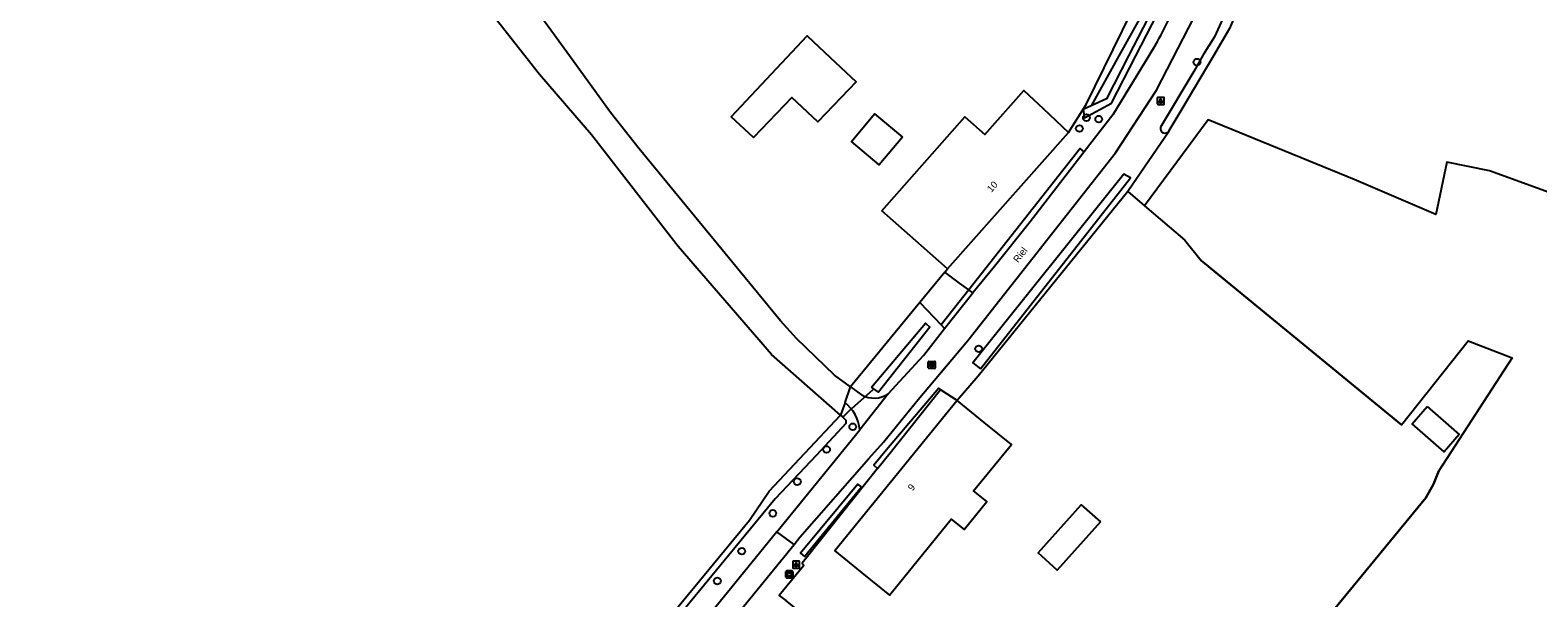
# Model space of a CAD drawing. Extents: x 163863 to 164644, y 379566 to 382155.
# Drawn here: x 164245.6 to 164462.3, y 381172.1 to 381253.7 of the extents above; entities that cross this region are included whole.
import ezdxf

# ---------------------------------------------------------------- set-up
doc = ezdxf.new("R2010")
doc.units = 0
for name, color, linetype in [('IMGEO_Boom', 7, 'Continuous'), ('IMGEO_Duiker', 7, 'Continuous'), ('IMGEO_Erf', 7, 'Continuous'), ('IMGEO_Grasland_agrarisch', 7, 'Continuous'), ('IMGEO_Grasland_overig', 7, 'Continuous'), ('IMGEO_Groenvoorziening', 7, 'Continuous'), ('IMGEO_Haag', 7, 'Continuous'), ('IMGEO_Hek', 7, 'Continuous'), ('IMGEO_Lichtpunt', 7, 'Continuous'), ('IMGEO_Openbare_ruimte_label', 7, 'Continuous'), ('IMGEO_Pand', 7, 'Continuous'), ('IMGEO_Pand_nummerreeks', 7, 'Continuous'), ('IMGEO_Rijbaan_lokaal_gesloten', 7, 'Continuous'), ('IMGEO_Rijbaan_lokaal_halfverhard', 7, 'Continuous'), ('IMGEO_Rioolput', 7, 'Continuous'), ('IMGEO_Verklikker', 7, 'Continuous'), ('IMGEO_Voetpad_gesloten', 7, 'Continuous'), ('IMGEO_Voetpad_open', 7, 'Continuous'), ('IMGEO_Waterloop', 7, 'Continuous')]:
    doc.layers.add(name, color=color, linetype=linetype)

msp = doc.modelspace()

# ---------------------------------------------------------------- linework, layer by layer
at = {"layer": 'IMGEO_Boom'}
for centre in [(164413.32, 381249.11), (164397.44, 381241.12), (164396.42, 381239.57), (164399.21, 381240.92), (164381.95, 381207.91), (164363.86, 381196.71), (164360.09, 381193.46), (164355.88, 381188.82), (164352.37, 381184.28), (164347.89, 381178.84), (164344.39, 381174.56)]:
    msp.add_circle(centre, 0.489, dxfattribs=at)
at = {"layer": 'IMGEO_Duiker'}
msp.add_lwpolyline([(164362.45, 381198.09), (164363.27, 381198.97), (164366.81, 381202.09)], dxfattribs=at)
at = {"layer": 'IMGEO_Erf'}
msp.add_lwpolyline([(164403.37, 381230.53), (164405.79, 381228.47)], dxfattribs=at)
at = {"layer": 'IMGEO_Grasland_agrarisch'}
for points in [[(164491.42, 381190.96), (164476.78, 381197.2), (164466.17, 381201.68), (164468.67, 381207.69), (164476.57, 381225.79), (164455.37, 381233.49), (164449.22, 381234.75), (164447.64, 381227.22), (164435.91, 381232.23), (164414.92, 381240.8), (164405.79, 381228.47)], [(164405.79, 381228.47), (164411.58, 381223.53), (164413.91, 381220.59), (164442.73, 381196.98), (164452.32, 381209.05), (164458.6, 381206.61), (164448.06, 381190.36), (164447.34, 381188.47), (164446.23, 381186.49), (164431.84, 381169.01), (164404.86, 381131.61), (164354.22, 381171.73)]]:
    msp.add_lwpolyline(points, dxfattribs=at)
at = {"layer": 'IMGEO_Grasland_overig'}
for points in [[(164362.1, 381198.39), (164352.18, 381207.09), (164338.77, 381222.6), (164326.32, 381238.65), (164318.83, 381247.33), (164310.33, 381258.14), (164307.18, 381263.52), (164299.42, 381274.81), (164284.28, 381292.99), (164286.58, 381295.47)], [(164363.54, 381202.45), (164361.21, 381204.13), (164355.77, 381209.41), (164353.46, 381211.92), (164333.15, 381236.67), (164329.04, 381241.88), (164323.16, 381250), (164316.87, 381258.7), (164310.95, 381266.61)], [(164394.86, 381239.02), (164397.4, 381243.03), (164407.78, 381264.26)], [(164377.08, 381218.93), (164377.46, 381219.39)], [(164373.51, 381214.58), (164363.54, 381202.45)], [(164362.74, 381200.21), (164362.1, 381198.39)]]:
    msp.add_lwpolyline(points, dxfattribs=at)
at = {"layer": 'IMGEO_Groenvoorziening'}
for points in [[(164409.26, 381239.26), (164409.33, 381239.2), (164403.37, 381230.53)], [(164403.37, 381230.53), (164381.86, 381203.99), (164378.85, 381200.5)], [(164378.85, 381200.5), (164376.58, 381201.96), (164376.48, 381202.06)], [(164367.41, 381190.7), (164357.36, 381178.07), (164356.6, 381177.11), (164356.84, 381176.79), (164353.3, 381172.46), (164354.22, 381171.73)]]:
    msp.add_lwpolyline(points, dxfattribs=at)
at = {"layer": 'IMGEO_Haag'}
msp.add_lwpolyline([(164411.34, 381270.45), (164408.93, 381262.31), (164402.11, 381250), (164398.13, 381242.82)], dxfattribs=at)
at = {"layer": 'IMGEO_Hek'}
for points in [[(164449.22, 381234.75), (164447.64, 381227.22), (164435.91, 381232.23), (164414.92, 381240.8)], [(164468.67, 381207.69), (164476.57, 381225.79), (164455.37, 381233.49), (164449.22, 381234.75)], [(164411.58, 381223.53), (164413.91, 381220.59)], [(164442.73, 381196.98), (164413.91, 381220.59)], [(164406.25, 381130.51), (164427.31, 381160.02), (164428.98, 381161.55), (164431.84, 381169.01), (164446.23, 381186.49), (164447.34, 381188.47), (164448.06, 381190.36)]]:
    msp.add_lwpolyline(points, dxfattribs=at)
at = {"layer": 'IMGEO_Lichtpunt'}
for p, q in [((164407.62, 381243.94), (164407.62, 381243.13)), ((164407.62, 381243.94), (164407.62, 381243.13)), ((164408.52, 381244.03), (164407.71, 381244.03)), ((164408.52, 381244.03), (164407.71, 381244.03)), ((164408.61, 381243.13), (164408.61, 381243.94)), ((164408.61, 381243.13), (164408.61, 381243.94)), ((164407.71, 381243.03), (164408.52, 381243.03)), ((164407.71, 381243.03), (164408.52, 381243.03)), ((164355.22, 381177.3), (164355.22, 381176.5)), ((164355.22, 381177.3), (164355.22, 381176.5)), ((164356.12, 381177.4), (164355.32, 381177.4)), ((164356.12, 381177.4), (164355.32, 381177.4)), ((164356.22, 381176.5), (164356.22, 381177.3)), ((164356.22, 381176.5), (164356.22, 381177.3)), ((164355.32, 381176.4), (164356.12, 381176.4)), ((164355.32, 381176.4), (164356.12, 381176.4))]:
    msp.add_line(p, q, dxfattribs=at)
for points in [[(164407.99, 381243.6), (164408.03, 381243.57), (164407.84, 381243.31), (164407.8, 381243.34), (164407.99, 381243.6)], [(164408.09, 381243.55), (164408.14, 381243.55), (164408.14, 381243.23), (164408.09, 381243.23), (164408.09, 381243.55)], [(164408.2, 381243.57), (164408.24, 381243.6), (164408.43, 381243.34), (164408.39, 381243.31), (164408.2, 381243.57)], [(164355.6, 381176.97), (164355.63, 381176.94), (164355.45, 381176.68), (164355.41, 381176.71), (164355.6, 381176.97)], [(164355.7, 381176.92), (164355.74, 381176.92), (164355.74, 381176.6), (164355.7, 381176.6), (164355.7, 381176.92)], [(164355.81, 381176.94), (164355.85, 381176.97), (164356.03, 381176.7), (164355.99, 381176.68), (164355.81, 381176.94)]]:
    msp.add_lwpolyline(points, dxfattribs=at)
for centre in [(164408.12, 381243.73), (164355.72, 381177.1)]:
    msp.add_circle(centre, 0.0994, dxfattribs=at)
for centre, start, end in [((164407.71, 381243.94), 90, 180), ((164407.71, 381243.94), 90, 180), ((164408.52, 381243.94), 0, 90), ((164408.52, 381243.94), 0, 90), ((164407.71, 381243.13), 180, 270), ((164407.71, 381243.13), 180, 270), ((164408.52, 381243.13), 270, 0), ((164408.52, 381243.13), 270, 360), ((164355.32, 381177.3), 90, 180), ((164355.32, 381177.3), 90, 180), ((164356.12, 381177.3), 0, 90), ((164356.12, 381177.3), 0, 90), ((164355.32, 381176.5), 180, 270), ((164355.32, 381176.5), 180, 270), ((164356.12, 381176.5), 270, 0), ((164356.12, 381176.5), 270, 360)]:
    msp.add_arc(centre, 0.0946, start, end, dxfattribs=at)
at = {"layer": 'IMGEO_Pand'}
for points in [[(164360.62, 381249.78), (164364.35, 381246.28), (164358.84, 381240.52), (164355.11, 381244.02), (164349.6, 381238.26), (164346.39, 381241.26), (164357.3, 381252.89), (164360.62, 381249.78)], [(164377.46, 381219.39), (164373.72, 381222.71), (164368.02, 381227.76), (164379.96, 381241.24), (164382.83, 381238.7), (164388.45, 381245.03), (164391.21, 381242.44), (164394.86, 381239.02)], [(164370.99, 381238.31), (164367.66, 381234.34), (164363.67, 381237.69), (164367, 381241.66), (164370.99, 381238.31)], [(164377.46, 381219.39), (164394.86, 381239.02)], [(164378.85, 381200.5), (164361.29, 381178.9), (164365.17, 381175.74), (164369.12, 381172.53), (164378.01, 381183.46), (164379.86, 381181.95), (164383.12, 381185.97), (164381.23, 381187.51), (164386.65, 381194.16), (164382.73, 381197.35), (164378.85, 381200.5)], [(164446.39, 381199.62), (164451, 381195.59), (164448.83, 381193.12), (164444.23, 381197.15), (164446.39, 381199.62)], [(164399.44, 381183.05), (164393.25, 381176.13), (164390.5, 381178.6), (164396.68, 381185.51), (164399.44, 381183.05)]]:
    msp.add_lwpolyline(points, dxfattribs=at)
at = {"layer": 'IMGEO_Rijbaan_lokaal_gesloten'}
for points in [[(164355.42, 381179.8), (164356.26, 381180.83), (164366.18, 381192.15), (164368.28, 381194.51), (164373.24, 381200.61), (164380.37, 381209.13), (164401.6, 381236.08), (164407.49, 381245.09), (164413.63, 381256.97), (164417.3, 381265.29), (164423.08, 381279.48), (164426.2, 381287.59), (164428.15, 381292.04), (164429.94, 381295.69), (164431.96, 381299.66)], [(164407.38, 381251.61), (164406.39, 381250), (164401.21, 381241.55), (164397.1, 381236.21)], [(164397.1, 381236.21), (164389.34, 381226.14), (164384.21, 381219.76), (164381.13, 381215.96)], [(164377.04, 381210.81), (164381.13, 381215.96)], [(164368.94, 381201.43), (164374.03, 381206.95), (164377.04, 381210.81)], [(164368.94, 381201.43), (164364.89, 381196.29)], [(164352.96, 381181.62), (164364.89, 381196.29)], [(164352.96, 381181.62), (164325.21, 381147.51), (164297.15, 381112.5), (164283.09, 381094.56), (164268.85, 381076.08), (164254.82, 381057.26), (164245.63, 381044.28)], [(164355.42, 381179.8), (164352.96, 381181.62)], [(164246.03, 381039.89), (164248.19, 381042.64), (164257.14, 381055.39), (164271.16, 381074.14), (164285.34, 381092.57), (164299.26, 381110.37), (164327.62, 381145.68), (164355.42, 381179.8)]]:
    msp.add_lwpolyline(points, dxfattribs=at)
msp.add_arc((164356.13, 381281.24), 59.19, 329.9611, 338.3322, dxfattribs=at)
at = {"layer": 'IMGEO_Rijbaan_lokaal_halfverhard'}
for points in [[(164362.74, 381200.21), (164363.54, 381202.45)], [(164363.54, 381202.45), (164365.13, 381201.29)]]:
    msp.add_lwpolyline(points, dxfattribs=at)
for centre, radius, start, end in [((164366.92, 381204.52), 3.69, 241.068, 303.2332), ((164358.9, 381195.56), 6.03, 6.9415, 50.4634)]:
    msp.add_arc(centre, radius, start, end, dxfattribs=at)
at = {"layer": 'IMGEO_Rioolput'}
for p, q in [((164374.69, 381205.18), (164374.69, 381206.03)), ((164374.77, 381206.1), (164375.62, 381206.1)), ((164375.62, 381205.1), (164374.77, 381205.1)), ((164375.18, 381205.88), (164375.21, 381205.88)), ((164375.2, 381205.32), (164375.18, 381205.32)), ((164375.7, 381206.03), (164375.7, 381205.18))]:
    msp.add_line(p, q, dxfattribs=at)
for points in [[(164374.69, 381205.18), (164374.69, 381206.03)], [(164374.77, 381206.1), (164375.62, 381206.1)], [(164375.62, 381205.1), (164374.77, 381205.1)], [(164375.28, 381205.8), (164375.03, 381205.8), (164375.03, 381205.4)], [(164375.03, 381205.4), (164375.16, 381205.4), (164375.16, 381205.57), (164375.17, 381205.57)], [(164375.21, 381205.72), (164375.16, 381205.72), (164375.16, 381205.64)], [(164375.16, 381205.64), (164375.21, 381205.64)], [(164375.21, 381205.54), (164375.28, 381205.4), (164375.42, 381205.4), (164375.36, 381205.53)], [(164375.7, 381206.03), (164375.7, 381205.18)]]:
    msp.add_lwpolyline(points, dxfattribs=at)
for centre, radius, start, end in [((164374.77, 381206.03), 0.0765, 91.552, 178.448), ((164374.77, 381206.03), 0.0765, 91.552, 178.448), ((164374.77, 381205.18), 0.0765, 181.552, 268.448), ((164374.77, 381205.18), 0.0765, 181.552, 268.448), ((164375.16, 381205.51), 0.0533, 26.0293, 88.6989), ((164375.21, 381205.63), 0.0964, 77.0061, 93.1865), ((164375.19, 381205.83), 0.19, 274.7715, 282.9687), ((164375.23, 381205.68), 0.0378, 276.6634, 79.6772), ((164375.28, 381205.69), 0.109, 350.3612, 89.416), ((164375.28, 381205.69), 0.112, 277.5842, 350.9817), ((164375.26, 381205.48), 0.108, 29.5134, 73.7905), ((164375.62, 381206.03), 0.0765, 1.552, 88.448), ((164375.62, 381206.03), 0.0765, 1.552, 88.448), ((164375.62, 381205.18), 0.0765, 271.552, 358.448), ((164375.62, 381205.18), 0.0765, 271.552, 358.448)]:
    msp.add_arc(centre, radius, start, end, dxfattribs=at)
for centre, major_axis, ratio, start_param, end_param in [((164375.18, 381205.6), (-0.387, 0.002), 0.722429, 4.712389, 7.853982), ((164375.21, 381205.6), (-0.39, 0.002), 0.717154, 1.570796, 4.712389)]:
    msp.add_ellipse(centre, major_axis=major_axis, ratio=ratio, start_param=start_param, end_param=end_param, dxfattribs=at)
at = {"layer": 'IMGEO_Verklikker'}
for p, q in [((164354.24, 381175.11), (164354.24, 381175.91)), ((164354.24, 381175.91), (164354.24, 381175.11)), ((164354.34, 381176.01), (164355.13, 381176.01)), ((164355.13, 381176.01), (164354.34, 381176.01)), ((164355.13, 381175.01), (164354.34, 381175.01)), ((164354.34, 381175.01), (164355.13, 381175.01)), ((164355.23, 381175.91), (164355.23, 381175.11)), ((164355.23, 381175.11), (164355.23, 381175.91))]:
    msp.add_line(p, q, dxfattribs=at)
for points in [[(164354.34, 381175.74), (164355.13, 381175.74), (164355.13, 381175.28), (164354.34, 381175.28), (164354.34, 381175.74)], [(164354.41, 381175.68), (164354.41, 381175.34), (164355.06, 381175.34), (164355.06, 381175.68), (164354.41, 381175.68)]]:
    msp.add_lwpolyline(points, dxfattribs=at)
for centre, start, end in [((164354.34, 381175.91), 90, 180), ((164354.34, 381175.91), 90, 180), ((164354.34, 381175.11), 180, 270), ((164354.34, 381175.11), 180, 270), ((164355.13, 381175.91), 0, 90), ((164355.13, 381175.91), 360, 90), ((164355.13, 381175.11), 270, 0), ((164355.13, 381175.11), 270, 0)]:
    msp.add_arc(centre, 0.1, start, end, dxfattribs=at)
at = {"layer": 'IMGEO_Voetpad_gesloten'}
for points in [[(164377.08, 381218.93), (164373.51, 381214.58)], [(164380.55, 381216.38), (164379.21, 381217.37), (164377.08, 381218.93)], [(164380.55, 381216.38), (164376.54, 381211.34)], [(164373.51, 381214.58), (164376.54, 381211.34)]]:
    msp.add_lwpolyline(points, dxfattribs=at)
at = {"layer": 'IMGEO_Voetpad_open'}
for points in [[(164397.1, 381236.21), (164396.56, 381236.69), (164380.55, 381216.38)], [(164381.13, 381215.96), (164380.55, 381216.38)], [(164376.54, 381211.34), (164377.04, 381210.81)]]:
    msp.add_lwpolyline(points, dxfattribs=at)
at = {"layer": 'IMGEO_Waterloop'}
for points in [[(164434.95, 381299.87), (164433.96, 381298.73), (164433.14, 381297.47), (164428.43, 381286.14), (164421.91, 381267.78), (164419.86, 381262.14), (164418.25, 381258.03), (164415.85, 381252.76), (164414.21, 381250.17), (164412.87, 381247.75), (164408.09, 381239.75)], [(164434.59, 381297.48), (164429.56, 381285.91), (164427.39, 381279.98), (164420.03, 381258.54), (164419.12, 381256.54), (164417.98, 381253.92), (164415.71, 381250), (164411.16, 381242.33), (164409.26, 381239.26)], [(164398.13, 381242.82), (164396.98, 381242.28), (164397.17, 381241.12), (164401.04, 381243.21), (164404.53, 381250), (164409.23, 381259.16)], [(164408.37, 381259.48), (164403.48, 381250), (164400.31, 381243.85), (164398.13, 381242.82)], [(164382.23, 381205.05), (164403.79, 381232.48), (164402.81, 381233.02), (164381.09, 381205.89), (164382.23, 381205.05)], [(164366.54, 381202.41), (164374.33, 381211.6), (164374.92, 381211.01), (164367.57, 381201.67), (164366.54, 381202.41)], [(164376.48, 381202.06), (164376.24, 381202.26), (164368.7, 381193.39), (164366.86, 381191.21), (164367.41, 381190.7)], [(164367.41, 381190.7), (164369.24, 381192.97), (164376.48, 381202.06)], [(164362.1, 381198.39), (164362.45, 381198.19), (164362.45, 381198.09), (164362.88, 381197.68), (164362.88, 381197.17), (164358.66, 381192.61), (164352.68, 381186.34), (164315.21, 381140.78), (164290.33, 381110.01), (164284.87, 381100.39), (164279.89, 381093.78), (164279.12, 381094.43), (164278.22, 381095.19)], [(164278.22, 381095.19), (164281.5, 381099.85), (164286.83, 381106.67), (164289.04, 381110.56), (164349.03, 381183.28), (164351.85, 381187.47), (164362.1, 381198.39)], [(164365.11, 381188.09), (164364.57, 381188.47), (164356.32, 381178.54), (164356.92, 381178.05), (164365.11, 381188.09)]]:
    msp.add_lwpolyline(points, dxfattribs=at)
msp.add_arc((164408.69, 381239.53), 0.632, 159.5014, 334.3516, dxfattribs=at)

# ---------------------------------------------------------------- texts
at = {"layer": 'IMGEO_Openbare_ruimte_label'}
msp.add_text('Riel', height=1, rotation=52.0295, dxfattribs=at).set_placement((164387.61, 381220.21))
at = {"layer": 'IMGEO_Pand_nummerreeks'}
for s, rotation, p in [('10', 48.4416, (164383.79, 381230.33)), ('9', 50.8901, (164372.44, 381187.41))]:
    msp.add_text(s, height=1, rotation=rotation, dxfattribs=at).set_placement(p)

doc.saveas('drawing.dxf')
